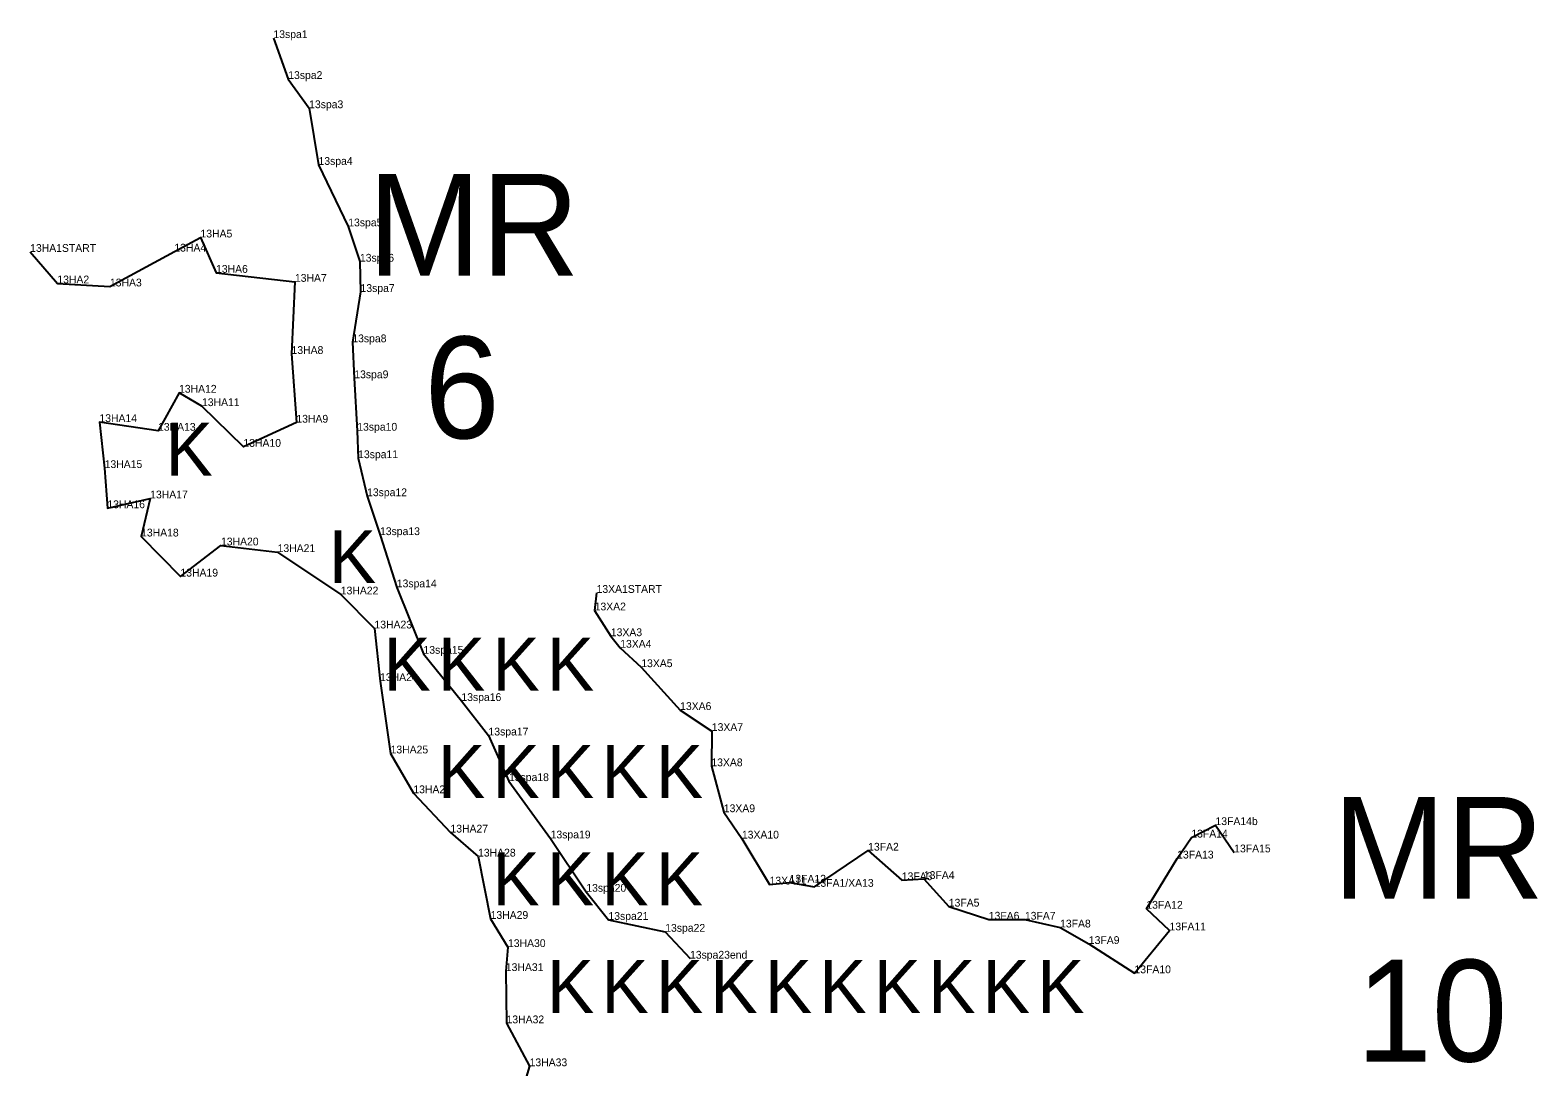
# Model space of a CAD drawing. Extents: x 2072529 to 2268812, y 436423 to 470008.
# Drawn here: x 2241251 to 2242220, y 450837 to 451503 of the extents above; entities that cross this region are included whole.
import ezdxf

# ---------------------------------------------------------------- set-up
doc = ezdxf.new("R2010")
doc.units = 0
for name, color, linetype in [('Old_Level_10', 7, 'Continuous'), ('Old_Level_20', 7, 'Continuous'), ('Old_Level_52', 7, 'Continuous'), ('Old_Level_55', 7, 'Continuous'), ('Old_Level_60', 7, 'Continuous'), ('Old_Level_62', 7, 'Continuous')]:
    doc.layers.add(name, color=color, linetype=linetype)

msp = doc.modelspace()

# ---------------------------------------------------------------- linework, layer by layer
at = {"layer": 'Old_Level_10'}
msp.add_lwpolyline([(2241407.812, 451497.466), (2241417.327, 451471.168), (2241430.755, 451452.426), (2241436.77, 451416.016), (2241455.9, 451376.517), (2241463.389, 451353.841), (2241463.785, 451334.385), (2241458.509, 451302.057), (2241459.768, 451278.962), (2241461.679, 451245.261), (2241462.243, 451227.618), (2241467.983, 451203.202), (2241476.293, 451178.191), (2241487.069, 451144.648), (2241504.229, 451101.984), (2241528.588, 451071.646), (2241546, 451049.505), (2241559.16, 451020.195), (2241585.938, 450983.378), (2241608.856, 450949.123), (2241623.068, 450931.045), (2241659.566, 450923.409), (2241675.49, 450906.13)], dxfattribs=at)
at = {"layer": 'Old_Level_20'}
for p, q in [((2241407.812, 451497.466), (2241407.812, 451497.466)), ((2241417.327, 451471.168), (2241417.327, 451471.168)), ((2241430.755, 451452.426), (2241430.755, 451452.426)), ((2241436.77, 451416.016), (2241436.77, 451416.016)), ((2241360.939, 451369.379), (2241360.939, 451369.379)), ((2241455.9, 451376.517), (2241455.9, 451376.517)), ((2241251.487, 451360.129), (2241251.487, 451360.129)), ((2241344.152, 451360.318), (2241344.152, 451360.318)), ((2241463.389, 451353.841), (2241463.389, 451353.841)), ((2241268.966, 451339.896), (2241268.966, 451339.896)), ((2241370.922, 451346.677), (2241370.922, 451346.677)), ((2241421.622, 451340.912), (2241421.622, 451340.912)), ((2241302.753, 451337.935), (2241302.753, 451337.935)), ((2241463.785, 451334.385), (2241463.785, 451334.385)), ((2241458.509, 451302.057), (2241458.509, 451302.057)), ((2241419.44, 451294.564), (2241419.44, 451294.564)), ((2241459.768, 451278.962), (2241459.768, 451278.962)), ((2241347.142, 451269.673), (2241347.142, 451269.673)), ((2241361.897, 451261.073), (2241361.897, 451261.073)), ((2241295.989, 451250.838), (2241295.989, 451250.838)), ((2241333.67, 451245.239), (2241333.67, 451245.239)), ((2241422.542, 451250.425), (2241422.542, 451250.425)), ((2241461.679, 451245.261), (2241461.679, 451245.261)), ((2241388.505, 451234.904), (2241388.505, 451234.904)), ((2241462.243, 451227.618), (2241462.243, 451227.618)), ((2241299.355, 451221.272), (2241299.355, 451221.272)), ((2241467.983, 451203.202), (2241467.983, 451203.202)), ((2241301.096, 451195.481), (2241301.096, 451195.481)), ((2241328.615, 451201.801), (2241328.615, 451201.801)), ((2241322.764, 451177.311), (2241322.764, 451177.311)), ((2241476.293, 451178.191), (2241476.293, 451178.191)), ((2241374.104, 451171.573), (2241374.104, 451171.573)), ((2241410.493, 451167.304), (2241410.493, 451167.304)), ((2241348.056, 451151.58), (2241348.056, 451151.58)), ((2241451.084, 451140.095), (2241451.084, 451140.095)), ((2241487.069, 451144.648), (2241487.069, 451144.648)), ((2241615.441, 451141.084), (2241615.441, 451141.084)), ((2241614.221, 451129.845), (2241614.221, 451129.845)), ((2241472.738, 451118.243), (2241472.738, 451118.243)), ((2241624.62, 451113.273), (2241624.62, 451113.273)), ((2241504.229, 451101.984), (2241504.229, 451101.984)), ((2241630.646, 451105.861), (2241630.646, 451105.861)), ((2241644.186, 451093.388), (2241644.186, 451093.388)), ((2241476.346, 451084.458), (2241476.346, 451084.458)), ((2241528.588, 451071.646), (2241528.588, 451071.646)), ((2241669.147, 451065.853), (2241669.147, 451065.853)), ((2241546, 451049.505), (2241546, 451049.505)), ((2241689.507, 451052.362), (2241689.507, 451052.362)), ((2241483.091, 451037.962), (2241483.091, 451037.962)), ((2241689.206, 451029.717), (2241689.206, 451029.717)), ((2241559.16, 451020.195), (2241559.16, 451020.195)), ((2241497.724, 451012.386), (2241497.724, 451012.386)), ((2241697.207, 451000.221), (2241697.207, 451000.221)), ((2242013.126, 450991.944), (2242013.126, 450991.944)), ((2241521.552, 450987.147), (2241521.552, 450987.147)), ((2241585.938, 450983.378), (2241585.938, 450983.378)), ((2241708.825, 450983.277), (2241708.825, 450983.277)), ((2241997.619, 450983.938), (2241997.619, 450983.938)), ((2241539.288, 450971.723), (2241539.288, 450971.723)), ((2241789.949, 450975.517), (2241789.949, 450975.517)), ((2241988.501, 450970.466), (2241988.501, 450970.466)), ((2242025.165, 450974.417), (2242025.165, 450974.417)), ((2241726.614, 450953.76), (2241726.614, 450953.76)), ((2241739.426, 450954.97), (2241739.426, 450954.97)), ((2241755.577, 450952.293), (2241755.577, 450952.293)), ((2241811.584, 450956.559), (2241811.584, 450956.559)), ((2241825.756, 450957.32), (2241825.756, 450957.32)), ((2241608.856, 450949.123), (2241608.856, 450949.123)), ((2241547.372, 450931.684), (2241547.372, 450931.684)), ((2241841.765, 450939.584), (2241841.765, 450939.584)), ((2241968.706, 450938.217), (2241968.706, 450938.217)), ((2241623.068, 450931.045), (2241623.068, 450931.045)), ((2241659.566, 450923.409), (2241659.566, 450923.409)), ((2241867.448, 450931.208), (2241867.448, 450931.208)), ((2241890.665, 450931.182), (2241890.665, 450931.182)), ((2241913.282, 450926.174), (2241913.282, 450926.174)), ((2241983.618, 450924.295), (2241983.618, 450924.295)), ((2241558.529, 450913.593), (2241558.529, 450913.593)), ((2241931.752, 450915.562), (2241931.752, 450915.562)), ((2241675.49, 450906.13), (2241675.49, 450906.13)), ((2241557.144, 450898.182), (2241557.144, 450898.182)), ((2241961.071, 450896.76), (2241961.071, 450896.76)), ((2241557.606, 450864.616), (2241557.606, 450864.616)), ((2241572.419, 450837.029), (2241572.419, 450837.029))]:
    msp.add_line(p, q, dxfattribs=at)
at = {"layer": 'Old_Level_52'}
for points in [[(2241251.487, 451360.129), (2241268.966, 451339.896), (2241302.753, 451337.935), (2241344.152, 451360.318), (2241360.939, 451369.379), (2241370.922, 451346.677), (2241421.622, 451340.912), (2241419.44, 451294.564), (2241422.542, 451250.425), (2241388.505, 451234.904), (2241361.897, 451261.073), (2241347.142, 451269.673), (2241333.67, 451245.239), (2241295.989, 451250.838), (2241299.355, 451221.272), (2241301.096, 451195.481), (2241328.615, 451201.801), (2241322.764, 451177.311), (2241348.056, 451151.58), (2241374.104, 451171.573), (2241410.493, 451167.304), (2241451.084, 451140.095), (2241472.738, 451118.243), (2241476.346, 451084.458), (2241483.091, 451037.962), (2241497.724, 451012.386), (2241521.552, 450987.147), (2241539.288, 450971.723), (2241547.372, 450931.684), (2241558.529, 450913.593), (2241557.144, 450898.182), (2241557.606, 450864.616), (2241572.419, 450837.029), (2241561.927, 450802.177)], [(2241615.441, 451141.084), (2241614.221, 451129.845), (2241624.62, 451113.273), (2241630.646, 451105.861), (2241644.186, 451093.388), (2241669.147, 451065.853), (2241689.507, 451052.362), (2241689.206, 451029.717), (2241697.207, 451000.221), (2241708.825, 450983.277), (2241726.614, 450953.76), (2241739.426, 450954.97), (2241755.577, 450952.293), (2241789.949, 450975.517), (2241811.584, 450956.559), (2241825.756, 450957.32), (2241841.765, 450939.584), (2241867.448, 450931.208), (2241890.665, 450931.182), (2241913.282, 450926.174), (2241931.752, 450915.562), (2241961.071, 450896.76), (2241983.618, 450924.295), (2241968.706, 450938.217), (2241988.501, 450970.466), (2241997.619, 450983.938), (2242013.126, 450991.944), (2242025.165, 450974.417)]]:
    msp.add_lwpolyline(points, dxfattribs=at)

# ---------------------------------------------------------------- texts
at = {"layer": 'Old_Level_55'}
for p in [(2241338.528, 451216.332), (2241443.528, 451147.332), (2241478.528, 451078.332), (2241513.528, 451078.332), (2241548.528, 451078.332), (2241583.528, 451078.332), (2241513.528, 451009.332), (2241548.528, 451009.332), (2241583.528, 451009.332), (2241618.528, 451009.332), (2241653.528, 451009.332), (2241548.528, 450940.332), (2241583.528, 450940.332), (2241618.528, 450940.332), (2241653.528, 450940.332), (2241583.528, 450871.332), (2241618.528, 450871.332), (2241653.528, 450871.332), (2241688.528, 450871.332), (2241723.528, 450871.332), (2241758.528, 450871.332), (2241793.528, 450871.332), (2241828.528, 450871.332), (2241863.528, 450871.332), (2241898.528, 450871.332)]:
    msp.add_text('K', height=34, dxfattribs=at).set_placement(p)
at = {"layer": 'Old_Level_60'}
for s, p in [('13spa1', (2241407.812, 451497.466)), ('13spa2', (2241417.327, 451471.168)), ('13spa3', (2241430.755, 451452.426)), ('13spa4', (2241436.77, 451416.016)), ('13spa5', (2241455.9, 451376.517)), ('13HA5', (2241360.939, 451369.379)), ('13HA1START', (2241251.487, 451360.129)), ('13HA4', (2241344.152, 451360.318)), ('13spa6', (2241463.389, 451353.841)), ('13HA6', (2241370.922, 451346.677)), ('13HA2', (2241268.966, 451339.896)), ('13HA3', (2241302.753, 451337.935)), ('13HA7', (2241421.622, 451340.912)), ('13spa7', (2241463.785, 451334.385)), ('13spa8', (2241458.509, 451302.057)), ('13HA8', (2241419.44, 451294.564)), ('13spa9', (2241459.768, 451278.962)), ('13HA12', (2241347.142, 451269.673)), ('13HA11', (2241361.897, 451261.073)), ('13HA14', (2241295.989, 451250.838)), ('13HA9', (2241422.542, 451250.425)), ('13HA13', (2241333.67, 451245.239)), ('13spa10', (2241461.679, 451245.261)), ('13HA10', (2241388.505, 451234.904)), ('13spa11', (2241462.243, 451227.618)), ('13HA15', (2241299.355, 451221.272)), ('13HA17', (2241328.615, 451201.801)), ('13spa12', (2241467.983, 451203.202)), ('13HA16', (2241301.096, 451195.481)), ('13HA18', (2241322.764, 451177.311)), ('13HA20', (2241374.104, 451171.573)), ('13spa13', (2241476.293, 451178.191)), ('13HA21', (2241410.493, 451167.304)), ('13HA19', (2241348.056, 451151.58)), ('13HA22', (2241451.084, 451140.095)), ('13spa14', (2241487.069, 451144.648)), ('13XA1START', (2241615.441, 451141.084)), ('13XA2', (2241614.221, 451129.845)), ('13HA23', (2241472.738, 451118.243)), ('13XA3', (2241624.62, 451113.273)), ('13spa15', (2241504.229, 451101.984)), ('13XA4', (2241630.646, 451105.861)), ('13XA5', (2241644.186, 451093.388)), ('13HA24', (2241476.346, 451084.458)), ('13spa16', (2241528.588, 451071.646)), ('13XA6', (2241669.147, 451065.853)), ('13spa17', (2241546, 451049.505)), ('13XA7', (2241689.507, 451052.362)), ('13HA25', (2241483.091, 451037.962)), ('13XA8', (2241689.206, 451029.717)), ('13spa18', (2241559.16, 451020.195)), ('13HA26', (2241497.724, 451012.386)), ('13XA9', (2241697.207, 451000.221)), ('13HA27', (2241521.552, 450987.147)), ('13FA14b', (2242013.126, 450991.944)), ('13spa19', (2241585.938, 450983.378)), ('13XA10', (2241708.825, 450983.277)), ('13FA2', (2241789.949, 450975.517)), ('13FA14', (2241997.619, 450983.938)), ('13HA28', (2241539.288, 450971.723)), ('13FA13', (2241988.501, 450970.466)), ('13FA15', (2242025.165, 450974.417)), ('13FA3', (2241811.584, 450956.559)), ('13FA4', (2241825.756, 450957.32)), ('13spa20', (2241608.856, 450949.123)), ('13XA11', (2241726.614, 450953.76)), ('13FA12', (2241739.426, 450954.97)), ('13FA1/XA13', (2241755.577, 450952.293)), ('13FA5', (2241841.765, 450939.584)), ('13FA12', (2241968.706, 450938.217)), ('13HA29', (2241547.372, 450931.684)), ('13spa21', (2241623.068, 450931.045)), ('13FA6', (2241867.448, 450931.208)), ('13FA7', (2241890.665, 450931.182)), ('13spa22', (2241659.566, 450923.409)), ('13FA8', (2241913.282, 450926.174)), ('13FA11', (2241983.618, 450924.295)), ('13HA30', (2241558.529, 450913.593)), ('13FA9', (2241931.752, 450915.562)), ('13HA31', (2241557.144, 450898.182)), ('13spa23end', (2241675.49, 450906.13)), ('13FA10', (2241961.071, 450896.76)), ('13HA32', (2241557.606, 450864.616)), ('13HA33', (2241572.419, 450837.029))]:
    msp.add_text(s, height=5, dxfattribs=at).set_placement(p)
at = {"layer": 'Old_Level_62'}
for s, p in [('MR', (2241468.561, 451344.894)), ('6', (2241504.662, 451240.35)), ('MR', (2242088.444, 450944.599)), ('10', (2242103.544, 450840.055))]:
    msp.add_text(s, height=65.34, dxfattribs=at).set_placement(p)

doc.saveas('drawing.dxf')
